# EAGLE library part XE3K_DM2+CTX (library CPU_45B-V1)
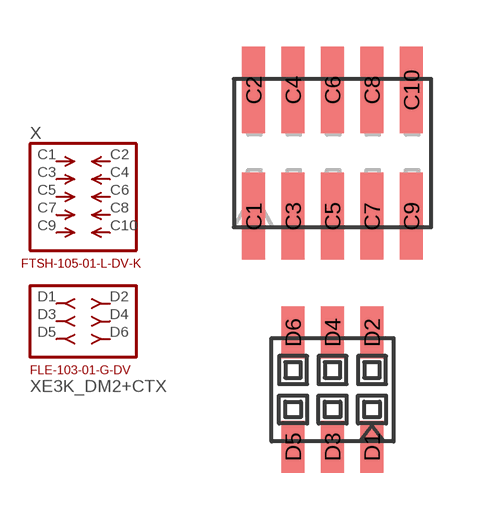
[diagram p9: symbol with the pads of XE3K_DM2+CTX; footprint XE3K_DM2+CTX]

Designator prefix X

## XE3K_DM2+CTX  [XE3K_DM2+CTX]
C1  C1  pas
C2  C2  pas
C3  C3  pas
C4  C4  pas
C5  C5  pas
C6  C6  pas
C7  C7  pas
C8  C8  pas
C9  C9  pas
C10  C10  pas
D1  D1  pas
D2  D2  pas
D3  D3  pas
D4  D4  pas
D5  D5  pas
D6  D6  pas

## Footprint XE3K_DM2+CTX (pad centres in mm)
smd 0.737 x 2.794: C1 -2.54,-2.032; C2 -2.54,2.032; C3 -1.27,-2.032; C4 -1.27,2.032; C5 0,-2.032; C6 0,2.032; C7 1.27,-2.032; C8 1.27,2.032; C9 2.54,-2.032; C10 2.54,2.032
smd 0.74 x 1.675: D1 1.27,-9.46; D2 1.27,-5.78; D3 0,-9.46; D4 0,-5.78; D5 -1.27,-9.46; D6 -1.27,-5.78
